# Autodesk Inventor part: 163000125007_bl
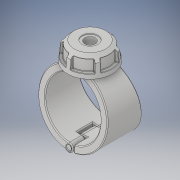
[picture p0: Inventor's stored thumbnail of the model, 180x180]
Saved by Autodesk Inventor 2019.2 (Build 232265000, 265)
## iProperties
Created: 2022-02
Part Number: 163000125007_bl
Material: Generic
Description: Plassadle Threaded 125x3/4''
Document SubType Name: Modeling
Designer: comp2
Density: 1 g/cm^3
Appearance: Default
Author: comp2
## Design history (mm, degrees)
derived "16300.ipt"
feature "Solid1::16300.ipt" dims "ScaleForDerivedMember" = 10
feature "Solid2::16300.ipt" dims "ScaleForDerivedMember" = 10
feature "Solid3::16300.ipt" dims "ScaleForDerivedMember" = 10
feature "Solid4::16300.ipt" dims "ScaleForDerivedMember" = 10
tag "TaggingFeature1"
body "Solid1"
body "Solid2"
body "Solid3"
body "Solid4"
other parameters: "d0" = 125 [user parameter], "d2" = 157 [user parameter], "d3" = 62.5 [user parameter], "d7" = 149.15 [user parameter], "d8" = 85 deg [user parameter], "d9" = 45 deg [user parameter], "d10" = 102 [user parameter], "d11" = 49 [user parameter], "d12" = 29.2495 [user parameter], "d13" = 42.84 [user parameter], "d14" = 36.1755 [user parameter], "d42" = 3.2 [user parameter], "d49" = 3.14 [user parameter], "d51" = 0 [user parameter], "d52" = 22.4 [user parameter], "d53" = 86.35 [user parameter], "d54" = 35 [user parameter], "d55" = 0 [user parameter], "d59" = 0 [user parameter], "d61" = 0 [user parameter], "d62" = 35 [user parameter], "d63" = 0 [user parameter], "d65" = 0 [user parameter], "d67" = 0 [user parameter], "d69" = 0 [user parameter], "d70" = 1 [user parameter], "d71" = 96 [user parameter], "d72" = 0 [user parameter], "d73" = 2 [user parameter], "d78" = 86.7 [user parameter], "d79" = 5.1 [user parameter], "d80" = 60 deg [user parameter], "d81" = 5.1 [user parameter], "d84" = 0 [user parameter], "d85" = 1 [user parameter], "d87" = 360 deg [user parameter], "d122" = 49 [user parameter], "d124" = 42.80128 [user parameter], "d125" = 2.08925 [user parameter], "d127" = 198 [user parameter], "d129" = 24.117 [user parameter], "d130" = 20.49945 [user parameter], "d131" = 31.85 [user parameter], "d132" = 45 deg [user parameter], "d133" = 22.295 [user parameter], "d134" = 12.0585 [user parameter], "d136" = 0 [user parameter], "d138" = 0 [user parameter], "d" = 125 [user parameter], "d1" = 25 [user parameter], "B" = 157 [user parameter], "E_" = 54 [user parameter], "E1" = 102 [user parameter], "H1" = 198 [user parameter], "H2" = 49 [user parameter], "H3" = 78 [user parameter], "H_costum" = 49 [user parameter], "Rp" = 24.117 [user parameter], "d128" = 41.785 [user parameter]
